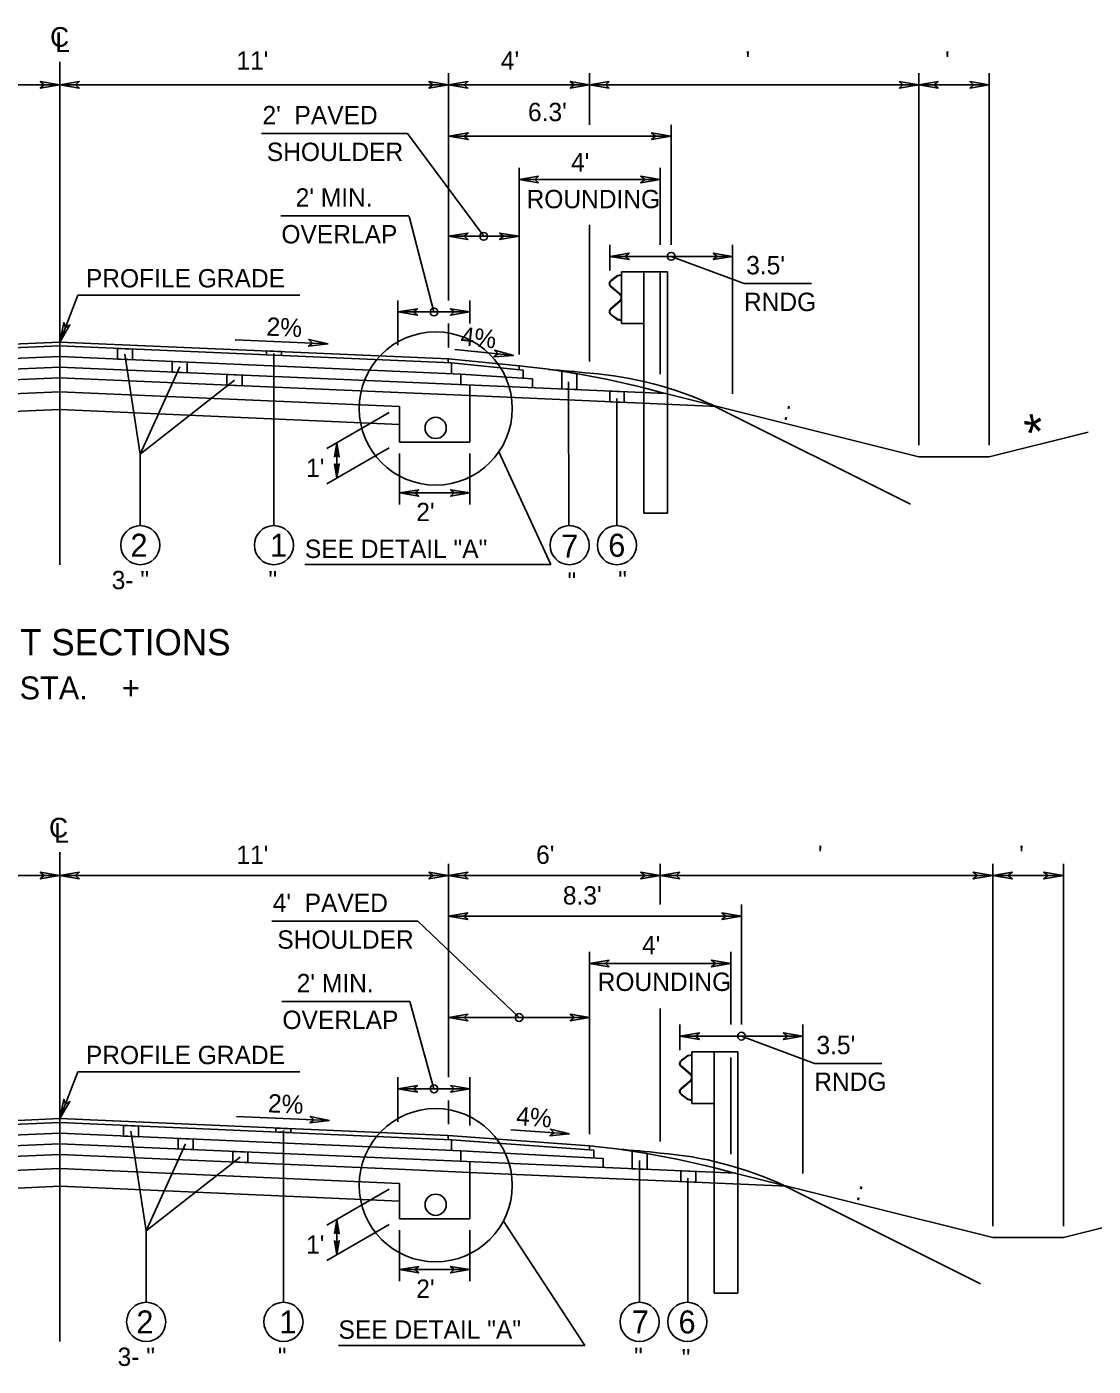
# Model space of a CAD drawing. Extents: x -592 to 1199, y -590 to 416.
# Drawn here: x -46.2 to 35.1, y 169.1 to 271.2 of the extents above; entities that cross this region are included whole.
import ezdxf

# ---------------------------------------------------------------- set-up
doc = ezdxf.new("R2010")
doc.units = 0
doc.layers.add('1', color=7, linetype='Continuous')
doc.layers.add('Des_ Drain_ Ftrs', color=7, linetype='Continuous')

msp = doc.modelspace()

# ---------------------------------------------------------------- linework, layer by layer
at = {"layer": '1'}
for p, q in [((-43.73, 230.22), (-43.73, 268.57)), ((-14.09, 250.37), (-14.09, 267.69)), ((-3.32, 263.77), (-3.32, 267.69)), ((21.78, 239.33), (21.78, 267.69)), ((27.16, 239.33), (27.16, 267.69)), ((-43.73, 266.81), (-73.36, 266.81)), ((-43.73, 266.81), (-14.09, 266.81)), ((-14.09, 266.81), (-3.32, 266.81)), ((-3.32, 266.81), (21.78, 266.81)), ((21.78, 266.81), (27.16, 266.81)), ((2.9, 254.61), (2.9, 263.77)), ((-17.21, 263.1), (-28.35, 263.1)), ((-11.4, 255.26), (-17.21, 263.1)), ((-14.07, 262.89), (2.9, 262.89)), ((-8.7, 246.26), (-8.7, 260.47)), ((2.07, 254.61), (2.07, 260.47)), ((-8.7, 259.59), (2.07, 259.59)), ((-26.86, 256.82), (-17.1, 256.82)), ((-15.19, 249.49), (-17.09, 256.77)), ((-3.32, 245.71), (-3.32, 256.14)), ((-14.09, 255.26), (-8.7, 255.26)), ((-1.79, 252.66), (-1.79, 254.61)), ((7.59, 243.26), (7.59, 254.61)), ((-1.79, 253.73), (7.59, 253.73)), ((2.9, 253.73), (8.46, 251.66)), ((-1.19, 252.27), (-1.71, 251.88)), ((-0.88, 252.32), (-1.19, 252.27)), ((-0.88, 252.29), (-1.18, 252.24)), ((-0.88, 252.55), (-0.88, 248.62)), ((-0.88, 252.55), (0.81, 252.55)), ((0.81, 252.55), (0.81, 234.15)), ((2.63, 252.55), (0.81, 252.55)), ((2.07, 244.74), (2.07, 252.53)), ((2.63, 252.55), (2.63, 234.15)), ((-1.72, 251.44), (-0.99, 250.81)), ((-1.71, 251.47), (-0.97, 250.83)), ((-1.18, 252.24), (-1.69, 251.85)), ((8.46, 251.66), (13.61, 251.66)), ((-43.73, 247.2), (-42.35, 250.77)), ((-25.43, 250.77), (-42.35, 250.77)), ((-17.94, 246.96), (-17.94, 250.37)), ((-12.45, 248.61), (-12.45, 250.37)), ((-0.99, 250.36), (-1.72, 249.72)), ((-0.97, 250.34), (-1.71, 249.7)), ((-0.91, 250.62), (-0.91, 250.55)), ((-0.88, 250.62), (-0.88, 250.55)), ((-17.94, 249.49), (-12.45, 249.49)), ((-1.71, 249.29), (-1.19, 248.9)), ((-1.69, 249.31), (-1.18, 248.93)), ((-14.09, 246.79), (-14.09, 248.61)), ((-1.19, 248.9), (-0.88, 248.85)), ((-1.18, 248.93), (-0.88, 248.88)), ((-0.88, 248.62), (0.81, 248.62)), ((-73.37, 245.91), (-43.73, 247.2)), ((-14.09, 245.91), (-43.73, 247.2)), ((-30.35, 247.37), (-23.27, 247.06)), ((-73.6, 245.6), (-43.73, 246.91)), ((-13.85, 245.6), (-43.73, 246.91)), ((-38.76, 246.28), (-37.59, 238.66)), ((-27.4, 246.33), (-27.4, 233.19)), ((-9.11, 246.18), (-13.59, 246.62)), ((-89.95, 243.27), (-43.73, 245.29)), ((-74.31, 244.76), (-43.73, 246.1)), ((-13.15, 244.76), (-43.73, 246.1)), ((2.49, 243.27), (-43.73, 245.29)), ((-34.58, 245.3), (-37.59, 238.66)), ((-14.1, 245.61), (-14.1, 245.91)), ((-8.7, 245.38), (-14.09, 245.91)), ((-8.4, 245.05), (-13.85, 245.6)), ((-13.85, 245.6), (-13.85, 244.79)), ((-8.7, 245.08), (-8.7, 245.38)), ((-93.87, 242.29), (-43.73, 244.48)), ((-17.93, 243.35), (-43.73, 244.48)), ((-30.41, 244.29), (-37.59, 238.66)), ((-7.67, 244.4), (-13.15, 244.76)), ((-13.15, 244.76), (-13.15, 243.95)), ((-8.4, 244.44), (-8.4, 245.05)), ((-7.67, 243.71), (-7.67, 244.4)), ((-4.93, 244.17), (-4.91, 233.19)), ((-1.79, 244.6), (-1.79, 244.6)), ((-69.62, 242.27), (-43.73, 243.4)), ((-17.83, 242.27), (-43.73, 243.4)), ((-12.45, 243.11), (-17.93, 243.35)), ((-12.45, 243.92), (-12.45, 243.11)), ((-12.45, 239.57), (-12.45, 243.11)), ((6.41, 242.29), (-12.45, 243.11)), ((2.07, 243.37), (21.78, 238.45)), ((-69.62, 240.92), (-43.73, 242.05)), ((-17.83, 240.92), (-43.73, 242.05)), ((-17.83, 239.57), (-17.83, 242.27)), ((-17.83, 242.27), (-17.83, 242.27)), ((-1.24, 242.89), (-1.24, 233.19)), ((6.09, 242.37), (21.15, 234.84)), ((-18.6, 241.83), (-23.35, 239.08)), ((34.7, 240.33), (27.16, 238.45)), ((-18.6, 239.13), (-23.37, 236.38)), ((-22.59, 239.52), (-22.61, 236.82)), ((-17.83, 239.57), (-12.45, 239.57)), ((-37.59, 238.66), (-37.59, 233.19)), ((-17.83, 238.69), (-17.83, 234.81)), ((-12.45, 238.69), (-12.45, 234.81)), ((-10.25, 238.82), (-6.27, 230.23)), ((21.78, 238.45), (27.16, 238.45)), ((-17.83, 235.69), (-12.45, 235.69)), ((2.63, 234.15), (0.81, 234.15)), ((-25.05, 230.23), (-6.27, 230.23)), ((-43.73, 171), (-43.73, 208.29)), ((-14.09, 191.14), (-14.09, 207.41)), ((2.07, 204.31), (2.07, 207.41)), ((27.42, 179.79), (27.42, 207.41)), ((32.81, 179.79), (32.81, 207.41)), ((-43.73, 206.53), (-73.36, 206.53)), ((-43.73, 206.53), (-14.09, 206.53)), ((-14.09, 206.53), (2.07, 206.53)), ((2.07, 206.53), (27.42, 206.53)), ((27.42, 206.53), (32.81, 206.53)), ((8.26, 195.15), (8.26, 204.31)), ((-14.1, 203.43), (8.26, 203.43)), ((-16.41, 203.04), (-27.55, 203.04)), ((-8.7, 195.7), (-16.41, 203.04)), ((-3.32, 186.79), (-3.32, 200.7)), ((7.46, 195.15), (7.46, 200.7)), ((-3.32, 199.82), (7.46, 199.82)), ((-26.79, 196.92), (-17.02, 196.92)), ((-15.19, 190.26), (-17.02, 196.92)), ((2.07, 186.24), (2.07, 196.38)), ((-14.09, 195.7), (-3.32, 195.7)), ((3.57, 193.2), (3.57, 195.15)), ((12.95, 183.8), (12.95, 195.15)), ((3.57, 194.27), (12.95, 194.27)), ((8.26, 194.27), (13.82, 192.2)), ((4.48, 193.09), (4.48, 189.15)), ((4.48, 193.09), (6.17, 193.09)), ((6.17, 193.09), (6.17, 174.69)), ((7.99, 193.09), (6.17, 193.09)), ((7.99, 193.09), (7.99, 174.69)), ((4.17, 192.8), (3.65, 192.41)), ((3.65, 192), (4.39, 191.37)), ((4.18, 192.77), (3.67, 192.39)), ((4.48, 192.86), (4.17, 192.8)), ((4.48, 192.83), (4.18, 192.77)), ((7.46, 185.27), (7.46, 192.65)), ((13.82, 192.2), (18.97, 192.2)), ((-43.73, 187.99), (-42.35, 191.56)), ((-25.43, 191.56), (-42.35, 191.56)), ((-17.94, 187.74), (-17.94, 191.14)), ((-12.45, 187.45), (-12.45, 191.14)), ((3.63, 191.98), (4.37, 191.34)), ((4.45, 191.16), (4.45, 191.08)), ((4.48, 191.16), (4.48, 191.08)), ((-17.94, 190.26), (-12.45, 190.26)), ((4.37, 190.89), (3.63, 190.26)), ((4.39, 190.87), (3.65, 190.24)), ((-14.09, 187.57), (-14.09, 189.38)), ((3.65, 189.83), (4.17, 189.44)), ((3.67, 189.85), (4.18, 189.46)), ((4.17, 189.44), (4.48, 189.38)), ((4.18, 189.46), (4.48, 189.41)), ((4.48, 189.15), (6.17, 189.15)), ((-73.37, 186.69), (-43.73, 187.99)), ((-14.1, 186.69), (-43.73, 187.99)), ((-30.24, 188.15), (-23.15, 187.84)), ((-73.6, 186.38), (-43.73, 187.69)), ((-13.85, 186.38), (-43.73, 187.69)), ((-38.31, 187.04), (-37.14, 179.42)), ((-26.67, 187.08), (-26.67, 173.97)), ((-4.85, 186.82), (-9.33, 187.14)), ((-95.28, 183.82), (-43.73, 186.07)), ((-74.31, 185.54), (-43.73, 186.88)), ((-13.15, 185.54), (-43.73, 186.88)), ((7.82, 183.82), (-43.73, 186.07)), ((-34.13, 186.06), (-37.14, 179.42)), ((-3.32, 185.91), (-14.1, 186.69)), ((-14.1, 186.39), (-14.1, 186.69)), ((-3.01, 185.59), (-13.85, 186.38)), ((-13.85, 186.38), (-13.85, 185.57)), ((-3.32, 185.61), (-3.32, 185.91)), ((-69.52, 184.13), (-43.73, 185.26)), ((-17.93, 184.13), (-43.73, 185.26)), ((-29.96, 185.04), (-37.14, 179.42)), ((-13.15, 185.54), (-13.15, 184.74)), ((-2.28, 184.94), (-13.15, 185.54)), ((-3.01, 184.98), (-3.01, 185.59)), ((-2.28, 184.26), (-2.28, 184.94)), ((3.57, 185.14), (3.57, 185.14)), ((-69.62, 183.05), (-43.73, 184.18)), ((-17.83, 183.05), (-43.73, 184.18)), ((-12.45, 183.89), (-17.93, 184.13)), ((-12.45, 184.7), (-12.45, 183.89)), ((-12.45, 180.35), (-12.45, 183.89)), ((11.74, 182.84), (-12.45, 183.89)), ((0.49, 184.8), (0.49, 173.97)), ((7.46, 183.91), (27.42, 178.91)), ((-69.62, 181.7), (-43.73, 182.83)), ((-17.83, 181.7), (-43.73, 182.83)), ((-17.83, 180.35), (-17.83, 183.05)), ((-17.83, 183.05), (-17.83, 183.05)), ((4.17, 183.44), (4.17, 173.97)), ((11.45, 182.91), (26.5, 175.38)), ((-18.6, 182.61), (-23.35, 179.86)), ((40.34, 180.8), (32.81, 178.91)), ((-18.6, 179.91), (-23.37, 177.16)), ((-22.59, 180.3), (-22.61, 177.59)), ((-17.83, 180.35), (-12.45, 180.35)), ((-9.89, 180.18), (-3.69, 170.7)), ((-37.14, 179.42), (-37.14, 173.97)), ((-17.83, 179.47), (-17.83, 175.59)), ((-12.45, 179.47), (-12.45, 175.59)), ((27.42, 178.91), (32.81, 178.91)), ((-17.83, 176.47), (-12.45, 176.47)), ((7.99, 174.69), (6.17, 174.69)), ((-22.48, 170.7), (-3.69, 170.7))]:
    msp.add_line(p, q, dxfattribs=at)
for points in [[(-39.33, 246.71), (-38.19, 246.66), (-38.19, 245.85), (-39.33, 245.9)], [(-27.97, 246.52), (-26.82, 246.47), (-26.82, 246.17), (-27.97, 246.22)], [(-35.16, 245.72), (-34.01, 245.67), (-34.01, 244.86), (-35.16, 244.91)], [(-30.98, 244.73), (-29.83, 244.68), (-29.83, 243.87), (-30.98, 243.92)], [(-5.45, 243.62), (-4.29, 243.57), (-4.29, 244.78), (-5.45, 244.97)], [(-0.68, 242.6), (-0.68, 243.41), (-1.77, 243.46), (-1.77, 242.64)], [(-38.88, 187.47), (-37.73, 187.42), (-37.73, 186.61), (-38.88, 186.66)], [(-27.25, 187.27), (-26.1, 187.22), (-26.1, 186.92), (-27.25, 186.97)], [(-34.7, 186.48), (-33.56, 186.43), (-33.56, 185.62), (-34.7, 185.67)], [(-30.53, 185.49), (-29.38, 185.44), (-29.38, 184.63), (-30.53, 184.68)], [(-0.08, 185.5), (1.06, 185.32), (1.06, 184.11), (-0.08, 184.16)], [(3.63, 184), (4.78, 183.95), (4.78, 183.14), (3.63, 183.19)]]:
    msp.add_lwpolyline(points, close=True, dxfattribs=at)
for centre, radius in [((-11.4, 255.26), 0.3), ((2.9, 253.73), 0.3), ((-15.19, 249.49), 0.3), ((-15.06, 242.13), 5.84), ((-15.06, 240.65), 0.808), ((-37.59, 231.71), 1.49), ((-27.4, 231.71), 1.49), ((-4.85, 231.71), 1.49), ((-1.24, 231.71), 1.49), ((-8.7, 195.7), 0.3), ((8.26, 194.27), 0.3), ((-15.19, 190.26), 0.3), ((-15.06, 182.91), 5.84), ((-15.06, 181.42), 0.808), ((-37.14, 172.49), 1.49), ((-26.67, 172.49), 1.49), ((0.49, 172.49), 1.49), ((4.13, 172.49), 1.49)]:
    msp.add_circle(centre, radius, dxfattribs=at)
for centre, radius, start, end in [((-1.54, 251.65), 0.278, 126.9799, 229.021), ((-1.54, 251.65), 0.249, 126.9799, 229.021), ((-1.16, 250.62), 0.249, 0, 49.0365), ((-1.16, 250.55), 0.249, 310.9635, 0), ((-1.16, 250.62), 0.278, 0, 49.0365), ((-1.16, 250.55), 0.278, 310.9635, 0), ((-1.54, 249.51), 0.278, 130.979, 233.0201), ((-1.54, 249.51), 0.249, 130.979, 233.0201), ((-15.59, 178.55), 67.19, 74.7593, 84.1179), ((-14.11, 144.16), 101.24, 83.8633, 85.6775), ((-5.41, 217.54), 27.37, 65.1374, 85.5513), ((3.82, 192.19), 0.278, 126.9799, 229.021), ((3.82, 192.19), 0.249, 126.9799, 229.021), ((4.2, 191.16), 0.249, 0, 49.0365), ((4.2, 191.08), 0.249, 310.9635, 0), ((4.2, 191.16), 0.278, 0, 49.0365), ((4.2, 191.08), 0.278, 310.9635, 0), ((3.82, 190.05), 0.278, 130.979, 233.0201), ((3.82, 190.05), 0.249, 130.979, 233.0201), ((-10.2, 119.08), 67.19, 74.7611, 84.1196), ((-8.75, 84.7), 101.24, 83.8633, 85.6775), ((-0.05, 158.07), 27.37, 65.1374, 85.5513)]:
    msp.add_arc(centre, radius, start, end, dxfattribs=at)
at = {"layer": 'Des_ Drain_ Ftrs'}
for points in [[(-43.73, 266.81), (-45.22, 266.56), (-44.92, 266.81), (-45.22, 267.06)], [(-43.73, 266.81), (-42.24, 266.56), (-42.53, 266.81), (-42.24, 267.06)], [(-14.09, 266.81), (-15.58, 266.56), (-15.29, 266.81), (-15.58, 267.06)], [(-14.09, 266.81), (-12.6, 266.56), (-12.9, 266.81), (-12.6, 267.06)], [(-3.32, 266.81), (-4.8, 266.56), (-4.51, 266.81), (-4.8, 267.06)], [(-3.32, 266.81), (-1.83, 266.56), (-2.12, 266.81), (-1.83, 267.06)], [(21.78, 266.81), (20.29, 266.56), (20.58, 266.81), (20.29, 267.06)], [(21.78, 266.81), (23.26, 266.56), (22.97, 266.81), (23.26, 267.06)], [(27.16, 266.81), (25.68, 266.56), (25.97, 266.81), (25.68, 267.06)], [(-14.07, 262.89), (-12.58, 262.64), (-12.88, 262.89), (-12.58, 263.14)], [(2.9, 262.89), (1.41, 262.64), (1.71, 262.89), (1.41, 263.14)], [(-8.7, 259.59), (-7.22, 259.34), (-7.51, 259.59), (-7.22, 259.84)], [(2.07, 259.59), (0.58, 259.34), (0.88, 259.59), (0.58, 259.84)], [(-14.09, 255.26), (-12.6, 255.01), (-12.9, 255.26), (-12.6, 255.51)], [(-8.7, 255.26), (-10.19, 255.01), (-9.9, 255.26), (-10.19, 255.51)], [(-1.79, 253.73), (-0.3, 253.49), (-0.6, 253.73), (-0.3, 253.98)], [(7.59, 253.73), (6.11, 253.49), (6.4, 253.73), (6.11, 253.98)], [(-17.94, 249.49), (-16.45, 249.24), (-16.74, 249.49), (-16.45, 249.74)], [(-12.45, 249.49), (-13.94, 249.24), (-13.64, 249.49), (-13.94, 249.74)], [(-43.73, 247.2), (-42.96, 248.5), (-43.3, 248.31), (-43.43, 248.68)], [(-23.27, 247.06), (-24.76, 246.88), (-24.46, 247.11), (-24.74, 247.38)], [(-9.11, 246.18), (-10.62, 246.07), (-10.3, 246.29), (-10.57, 246.57)], [(-22.59, 239.52), (-22.78, 238.44), (-22.6, 238.65), (-22.42, 238.44)], [(-22.61, 236.82), (-22.78, 237.9), (-22.61, 237.69), (-22.42, 237.9)], [(-17.83, 235.69), (-16.35, 235.44), (-16.64, 235.69), (-16.35, 235.94)], [(-12.45, 235.69), (-13.93, 235.44), (-13.64, 235.69), (-13.93, 235.94)], [(-43.73, 206.53), (-45.22, 206.28), (-44.92, 206.53), (-45.22, 206.77)], [(-43.73, 206.53), (-42.24, 206.28), (-42.53, 206.53), (-42.24, 206.77)], [(-14.09, 206.53), (-15.58, 206.28), (-15.29, 206.53), (-15.58, 206.77)], [(-14.09, 206.53), (-12.6, 206.28), (-12.9, 206.53), (-12.6, 206.77)], [(2.07, 206.53), (0.58, 206.28), (0.88, 206.53), (0.58, 206.77)], [(2.07, 206.53), (3.56, 206.28), (3.27, 206.53), (3.56, 206.77)], [(27.42, 206.53), (25.93, 206.28), (26.23, 206.53), (25.93, 206.77)], [(27.42, 206.53), (28.91, 206.28), (28.61, 206.53), (28.91, 206.77)], [(32.81, 206.53), (31.32, 206.28), (31.62, 206.53), (31.32, 206.77)], [(-14.1, 203.43), (-12.61, 203.18), (-12.91, 203.43), (-12.61, 203.67)], [(8.26, 203.43), (6.77, 203.18), (7.07, 203.43), (6.77, 203.67)], [(-3.32, 199.82), (-1.83, 199.57), (-2.12, 199.82), (-1.83, 200.06)], [(7.46, 199.82), (5.97, 199.57), (6.27, 199.82), (5.97, 200.06)], [(-14.09, 195.7), (-12.6, 195.45), (-12.9, 195.7), (-12.6, 195.95)], [(-3.32, 195.7), (-4.8, 195.45), (-4.51, 195.7), (-4.8, 195.95)], [(3.57, 194.27), (5.06, 194.02), (4.76, 194.27), (5.06, 194.52)], [(12.95, 194.27), (11.46, 194.02), (11.76, 194.27), (11.46, 194.52)], [(-17.94, 190.26), (-16.45, 190.01), (-16.74, 190.26), (-16.45, 190.51)], [(-12.45, 190.26), (-13.94, 190.01), (-13.64, 190.26), (-13.94, 190.51)], [(-43.73, 187.99), (-42.96, 189.29), (-43.3, 189.1), (-43.43, 189.46)], [(-23.15, 187.84), (-24.65, 187.66), (-24.35, 187.89), (-24.63, 188.15)], [(-4.85, 186.82), (-6.35, 186.68), (-6.04, 186.9), (-6.31, 187.17)], [(-22.59, 180.3), (-22.78, 179.22), (-22.6, 179.43), (-22.42, 179.21)], [(-22.61, 177.59), (-22.78, 178.68), (-22.61, 178.46), (-22.42, 178.68)], [(-17.83, 176.47), (-16.35, 176.22), (-16.64, 176.47), (-16.35, 176.72)], [(-12.45, 176.47), (-13.93, 176.22), (-13.64, 176.47), (-13.93, 176.72)]]:
    msp.add_lwpolyline(points, close=True, dxfattribs=at)

# ---------------------------------------------------------------- texts
at = {"layer": '1'}
for s, height, p in [("11'", 1.4, (-30.26, 267.96)), ("4'", 1.4, (-10.09, 267.96)), ("  '", 1.4, (7.53, 267.96)), (" '", 1.4, (23.27, 267.96)), ("2'  PAVED", 1.4, (-28.27, 263.8)), ("6.3'", 1.4, (-8.02, 264.04)), ('SHOULDER', 1.4, (-27.94, 261)), ("4'", 1.4, (-4.74, 260.2)), ("2' MIN.", 1.4, (-25.74, 257.52)), ('ROUNDING', 1.4, (-8.13, 257.4)), ('OVERLAP', 1.4, (-26.83, 254.72)), ("3.5'", 1.4, (8.62, 252.36)), ('PROFILE GRADE', 1.4, (-41.74, 251.36)), ('RNDG', 1.4, (8.45, 249.56)), ("2'", 1.4, (-16.54, 233.54)), ('2', 1.75, (-38.34, 230.83)), ('1', 1.75, (-27.7, 230.83)), ('SEE DETAIL "A"', 1.4, (-25.04, 230.73)), ('7', 1.75, (-5.49, 230.76)), ('6', 1.75, (-1.9, 230.83)), ('3- "', 1.4, (-39.77, 228.35)), (' "', 1.4, (-28.34, 228.35)), (' "', 1.4, (-5.53, 228.25)), (' "', 1.4, (-1.66, 228.35)), ('TANGENT SECTIONS', 2, (-57.9, 223.31)), ('STA.    +      TO STA.    +     ', 1.75, (-63.76, 219.95)), ("11'", 1.4, (-30.26, 207.41)), ("6'", 1.4, (-7.4, 207.41)), ("  '", 1.4, (13.05, 207.41)), (" '", 1.4, (28.92, 207.41)), ("8.3'", 1.4, (-5.36, 204.31)), ("4'  PAVED", 1.4, (-27.49, 203.74)), ('SHOULDER', 1.4, (-27.14, 200.94)), ("4'", 1.4, (0.68, 200.52)), ("2' MIN.", 1.4, (-25.66, 197.62)), ('ROUNDING', 1.4, (-2.71, 197.72)), ('OVERLAP', 1.4, (-26.75, 194.82)), ("3.5'", 1.4, (13.98, 192.9)), ('PROFILE GRADE', 1.4, (-41.74, 192.14)), ('RNDG', 1.4, (13.81, 190.1)), ("2'", 1.4, (-16.54, 174.32)), ('2', 1.75, (-37.89, 171.61)), ('1', 1.75, (-26.98, 171.61)), ('SEE DETAIL "A"', 1.4, (-22.47, 171.2)), ('7', 1.75, (-0.1, 171.61)), ('6', 1.75, (3.46, 171.61)), ('3- "', 1.4, (-39.32, 169.13)), (' "', 1.4, (-27.62, 169.13)), (' "', 1.4, (-0.45, 169.13)), (' "', 1.4, (3.18, 169.03))]:
    msp.add_text(s, height=height, dxfattribs=at).set_placement(p)
for s, height, rotation, p in [('2%', 1.4, 357.3765, (-27.99, 247.69)), ('4%', 1.4, 354.1268, (-13.21, 246.98)), (' : ', 1.4, 345.7718, (10.87, 241.46)), ('*', 2.8, 12.8479, (30.25, 238.8)), ("1'", 1.4, 0.1438, (-24.94, 236.91)), ('2%', 1.4, 357.376, (-27.88, 188.47)), ('4%', 1.4, 355.5936, (-8.96, 187.51)), (' : ', 1.4, 345.7718, (16.39, 181.96)), ("1'", 1.4, 0.1438, (-24.94, 177.68))]:
    msp.add_text(s, height=height, rotation=rotation, dxfattribs=at).set_placement(p)
at = {"layer": 'Des_ Drain_ Ftrs'}
for s, p in [('C', (-44.47, 269.71)), ('L', (-44.07, 269.31)), ('C', (-44.55, 209.42)), ('L', (-44.16, 209.02))]:
    msp.add_text(s, height=1.5, dxfattribs=at).set_placement(p)

doc.saveas('drawing.dxf')
